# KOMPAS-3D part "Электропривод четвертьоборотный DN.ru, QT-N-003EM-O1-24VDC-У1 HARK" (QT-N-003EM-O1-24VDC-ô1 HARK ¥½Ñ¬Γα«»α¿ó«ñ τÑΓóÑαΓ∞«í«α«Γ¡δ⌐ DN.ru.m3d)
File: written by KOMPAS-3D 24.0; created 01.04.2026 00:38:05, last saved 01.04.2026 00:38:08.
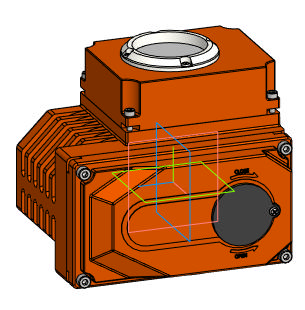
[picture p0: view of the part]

Document properties: Автор: DN.RU; Полное имя файла: D:\PROJECT CAD\DN.RU\...195\Исходники\24В\QT-N-003EM-O1-24VDC-У1 HARK Электропривод четвертьоборотный DN.ru\QT-N-003EM-O1-24VDC-У1 HARK Электропривод четвертьоборотный DN.ru.m3d

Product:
- Body: Твердое тело1  | qty 1
    Масса: 8.093373
- Part/product: Электропривод четвертьоборотный DN.ru  | designation QT-N-003EM-O1-24VDC-У1 HARK
    Масса: 2.1
    Раздел спецификации: Прочие изделия
    Комментарий: D300-05869
    Примечание: D300-05869
    additional columns: Типовые

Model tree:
1. Твердое тело1  (labels: Твердое тело1)

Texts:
  QT-N-003EM-O1-24VDC-У1 HARK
